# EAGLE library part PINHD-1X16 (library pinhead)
PIN HEADER
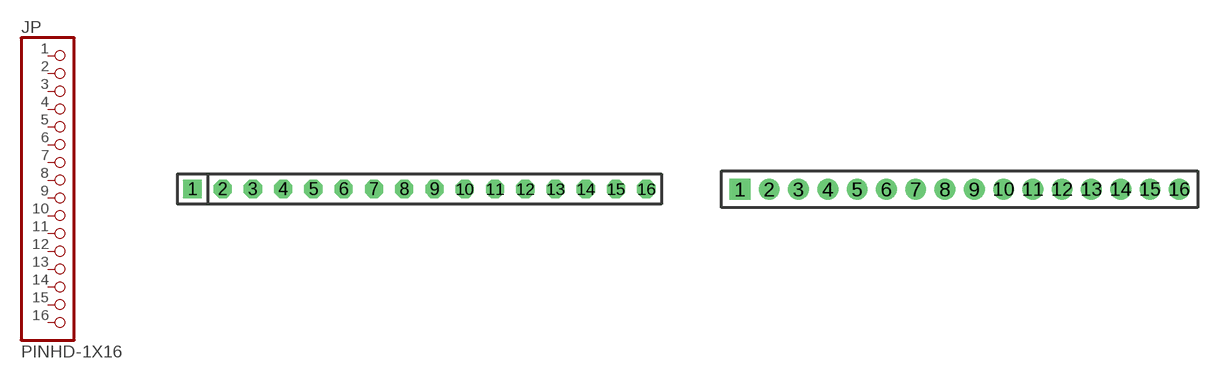
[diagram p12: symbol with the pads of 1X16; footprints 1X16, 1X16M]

Designator prefix JP

## PINHD-1X16  [1X16]
1  1  pas
2  2  pas
3  3  pas
4  4  pas
5  5  pas
6  6  pas
7  7  pas
8  8  pas
9  9  pas
10  10  pas
11  11  pas
12  12  pas
13  13  pas
14  14  pas
15  15  pas
16  16  pas

## PINHD-1X16M  [1X16M]
Pads as for 1X16

## Footprint 1X16 (pad centres in mm)
PIN HEADER - 0.1"
drill 1.016 square: 1 -19.05,0
drill 1.016 octagon: 2 -16.51,0; 3 -13.97,0; 4 -11.43,0; 5 -8.89,0; 6 -6.35,0; 7 -3.81,0; 8 -1.27,0; 9 1.27,0; 10 3.81,0; 11 6.35,0; 12 8.89,0; 13 11.43,0; 14 13.97,0; 15 16.51,0; 16 19.05,0

## Footprint 1X16M (pad centres in mm)
PIN HEADER - 2MM"
drill 0.914 square: 1 -15,0
drill 0.914 round: 2 -13,0; 3 -11,0; 4 -9,0; 5 -7,0; 6 -5,0; 7 -3,0; 8 -1,0; 9 1,0; 10 3,0; 11 5,0; 12 7,0; 13 9,0; 14 11,0; 15 13,0; 16 15,0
